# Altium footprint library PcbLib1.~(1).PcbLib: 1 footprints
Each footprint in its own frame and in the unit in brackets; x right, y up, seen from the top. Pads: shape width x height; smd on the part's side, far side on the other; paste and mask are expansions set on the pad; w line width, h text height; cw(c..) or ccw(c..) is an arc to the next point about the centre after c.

## TP4056Module [mm]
